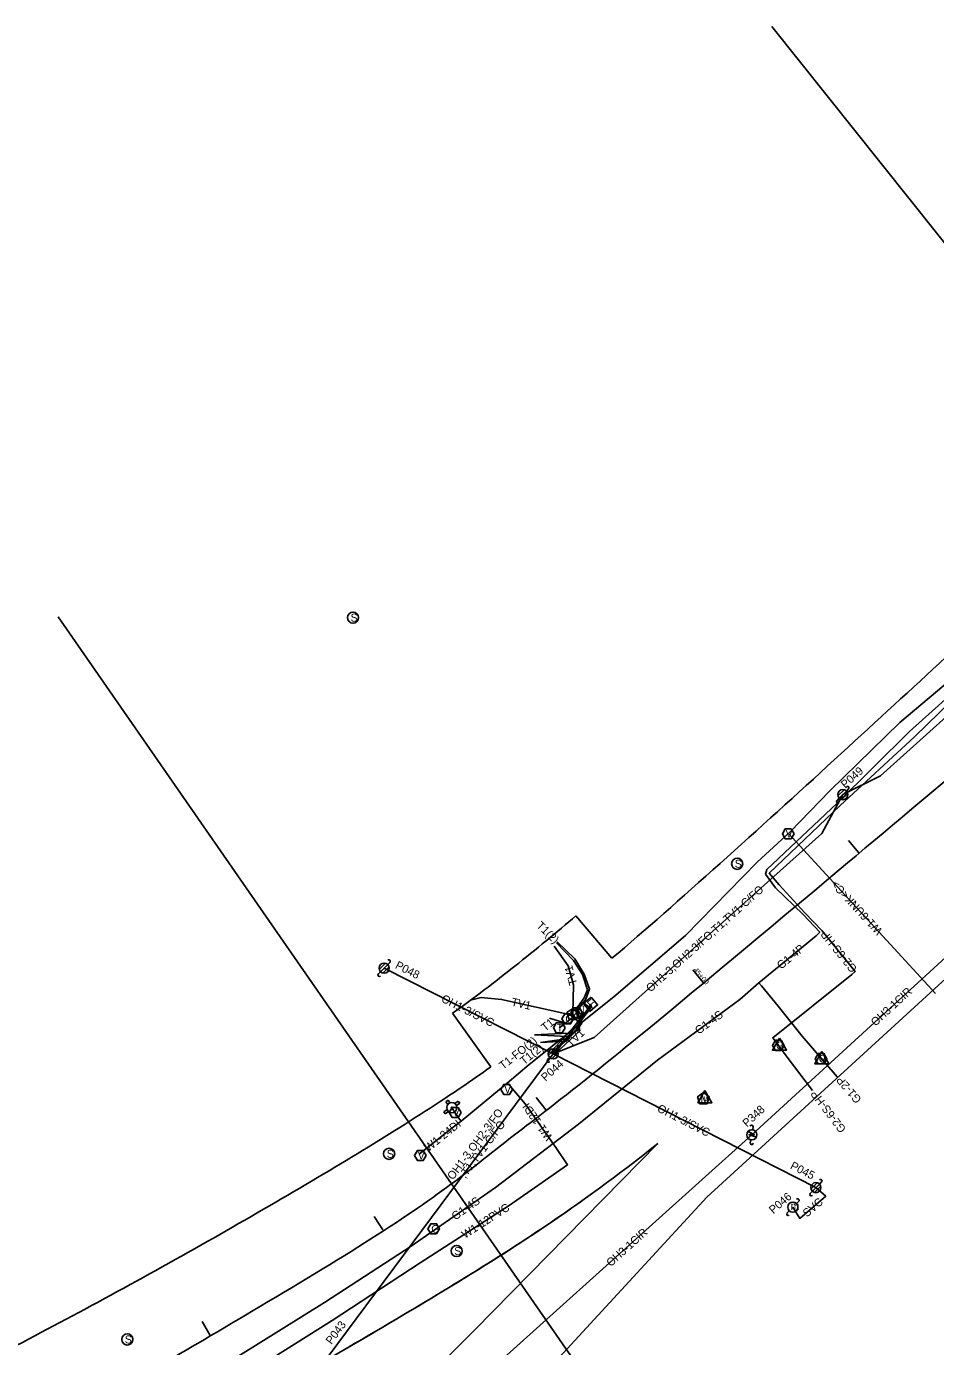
# Model space of a CAD drawing. Extents: x 1991878 to 2008544, y 770238 to 1141211.
# Drawn here: x 2006512 to 2006961, y 1140559 to 1141211 of the extents above; entities that cross this region are included whole.
import ezdxf

# ---------------------------------------------------------------- set-up
doc = ezdxf.new("R2010")
doc.units = 0
for name, color, linetype in [('RD_EX_SU_Gas', 7, 'Continuous'), ('RD_EX_SU_H2O', 7, 'Continuous'), ('RD_EX_SU_Misc', 7, 'Continuous'), ('RD_EX_SU_Ovhd', 7, 'Continuous'), ('RD_EX_SU_Pole', 7, 'Continuous'), ('RD_EX_SU_Sewer', 7, 'Continuous'), ('RD_EX_SU_SwpLmt', 7, 'Continuous'), ('RD_EX_SU_Telecom', 7, 'Continuous'), ('RD_EX_SU_TX_Gas', 7, 'Continuous'), ('RD_EX_SU_TX_H2O', 7, 'Continuous'), ('RD_EX_SU_TX_Ovhd', 7, 'Continuous'), ('RD_EX_SU_TX_Pole', 7, 'Continuous'), ('RD_EX_SU_TX_Telecom', 7, 'Continuous'), ('RD_HC_Cl', 7, 'Continuous')]:
    doc.layers.add(name, color=color, linetype=linetype)

msp = doc.modelspace()

# ---------------------------------------------------------------- linework, layer by layer
at = {"layer": 'RD_EX_SU_Gas'}
for points in [[(2006873.5, 1140738.51), (2006901.73, 1140761.75), (2006903.56, 1140763.42), (2006895.31, 1140772.28), (2006881.72, 1140785.43), (2006876.81, 1140792.08), (2006877.46, 1140794.49), (2006912.15, 1140827.15), (2006947.89, 1140862.5), (2006979.76, 1140891.26), (2006994.33, 1140904.09), (2007020.55, 1140929.45), (2007033.7, 1140941.3), (2007049.4, 1140950.39), (2007052.71, 1140953.47), (2007059.51, 1140959.79), (2007065.74, 1140966.97), (2007091.55, 1141000.3), (2007120.95, 1141038.48), (2007133.17, 1141051.57), (2007138.1, 1141057.67), (2007139.29, 1141058.85)], [(2006899.93, 1140685.24), (2006887.92, 1140701.03), (2006882.38, 1140708.6), (2006880.33, 1140711.39), (2006919.49, 1140742.59), (2006920.99, 1140744.01), (2006904.73, 1140764.19), (2006896.21, 1140773.09), (2006883.59, 1140786.79), (2006878.67, 1140792.56), (2006913.63, 1140826.04), (2006950.43, 1140859.88), (2006981.33, 1140890.04)], [(2006873.5, 1140738.51), (2006864.14, 1140730.25), (2006823.41, 1140700.36), (2006784.38, 1140668.66), (2006743.46, 1140637.37), (2006701.74, 1140608.41), (2006659, 1140580.57), (2006616.24, 1140554.03)], [(2006873.5, 1140738.51), (2006874.73, 1140736.92), (2006883.01, 1140727.02), (2006894.97, 1140712.14), (2006912.21, 1140692)]]:
    msp.add_lwpolyline(points, dxfattribs=at)
for points in [[(2006884.59, 1140705.08), (2006886.03, 1140707.58), (2006884.59, 1140710.08), (2006881.7, 1140710.08), (2006880.26, 1140707.58), (2006881.7, 1140705.08)], [(2006905.67, 1140698.51), (2006907.12, 1140701.01), (2006905.67, 1140703.51), (2006902.79, 1140703.51), (2006901.34, 1140701.01), (2006902.79, 1140698.51)], [(2006714.33, 1140614.5), (2006715.78, 1140617), (2006714.33, 1140619.5), (2006711.45, 1140619.5), (2006710, 1140617), (2006711.45, 1140614.5)]]:
    msp.add_lwpolyline(points, close=True, dxfattribs=at)
at = {"layer": 'RD_EX_SU_H2O'}
for p, q in [((2006960.71, 1140733.22), (2006888.13, 1140812.24)), ((2006720, 1140680.51), (2006718.99, 1140679.76)), ((2006718.99, 1140679.76), (2006719.94, 1140678.47)), ((2006720.97, 1140679.19), (2006720, 1140680.51)), ((2006725.01, 1140680.06), (2006723.38, 1140678.86)), ((2006724.16, 1140677.87), (2006725.76, 1140679.05)), ((2006725.76, 1140679.05), (2006725.01, 1140680.06)), ((2006719.5, 1140675.98), (2006717.92, 1140674.81)), ((2006717.92, 1140674.81), (2006718.67, 1140673.8)), ((2006718.67, 1140673.8), (2006720.21, 1140674.94))]:
    msp.add_line(p, q, dxfattribs=at)
for points in [[(2006705.8, 1140653.82), (2006721.81, 1140666.7), (2006726.48, 1140670.22), (2006749.2, 1140688.87), (2006760.06, 1140698.18), (2006801.94, 1140731.48), (2006837.34, 1140761.88), (2006872.75, 1140798.11), (2006888.92, 1140812.96), (2006908.58, 1140833.31), (2006943.2, 1140866.93), (2006990.62, 1140906.95), (2007018.28, 1140931.47), (2007022.75, 1140936), (2007039, 1140940.71), (2007059.99, 1140944.12), (2007094.46, 1140950.28), (2007154.59, 1140961.32), (2007180.73, 1140965.17), (2007208.8, 1140965.18), (2007231.59, 1140963.11), (2007245.06, 1140960.58), (2007248.47, 1140957.93), (2007283.51, 1140922.44)], [(2006749.33, 1140688.98), (2006750.78, 1140687.21), (2006758.08, 1140678.71), (2006773.28, 1140657.14), (2006779.04, 1140648.68), (2006750.2, 1140628.51), (2006706.32, 1140600.17), (2006662.73, 1140571.78), (2006621.15, 1140545.52)], [(2006726.46, 1140670.2), (2006725.68, 1140671.16), (2006722.55, 1140675.72), (2006721.87, 1140676.84)]]:
    msp.add_lwpolyline(points, dxfattribs=at)
for points in [[(2006890.87, 1140812.01), (2006889.43, 1140814.51), (2006886.54, 1140814.51), (2006885.1, 1140812.01), (2006886.54, 1140809.51), (2006889.43, 1140809.51)], [(2006751.87, 1140685.85), (2006750.43, 1140688.35), (2006747.54, 1140688.35), (2006746.1, 1140685.85), (2006747.54, 1140683.35), (2006750.43, 1140683.35)], [(2006846.11, 1140684.32), (2006843.21, 1140682.21), (2006844.32, 1140678.8), (2006847.9, 1140678.8), (2006849.01, 1140682.21)], [(2006726.42, 1140674.41), (2006724.97, 1140676.9), (2006722.09, 1140676.9), (2006720.64, 1140674.41), (2006722.09, 1140671.91), (2006724.97, 1140671.91)], [(2006709.21, 1140653.18), (2006707.76, 1140655.68), (2006704.88, 1140655.68), (2006703.43, 1140653.18), (2006704.88, 1140650.68), (2006707.76, 1140650.68)]]:
    msp.add_lwpolyline(points, close=True, dxfattribs=at)
for radius in [2.52, 0.315]:
    msp.add_circle((2006721.87, 1140676.84), radius, dxfattribs=at)
for start, end in [(110.76407, 139.73131), (24.20353, 53.17985), (199.85724, 228.83356)]:
    msp.add_arc((2006721.87, 1140676.84), 2.52, start, end, dxfattribs=at)
at = {"layer": 'RD_EX_SU_Misc'}
for points in [[(2006883.65, 1140711.2), (2006880.18, 1140705.2), (2006887.11, 1140705.2)], [(2006904.57, 1140704.52), (2006901.1, 1140698.52), (2006908.03, 1140698.52)], [(2006846.88, 1140685.3), (2006843.41, 1140679.3), (2006850.34, 1140679.3)]]:
    msp.add_lwpolyline(points, close=True, dxfattribs=at)
at = {"layer": 'RD_EX_SU_Ovhd'}
for p, q in [((2007017.86, 1140798.94), (2006870.01, 1140663.43)), ((2006688.44, 1140745.71), (2006771.97, 1140703.38)), ((2006660.79, 1140553.98), (2006771.97, 1140703.38)), ((2006901.69, 1140637.35), (2006771.97, 1140703.38)), ((2006870.01, 1140663.43), (2006747.45, 1140553.1))]:
    msp.add_line(p, q, dxfattribs=at)
for points in [[(2006914.95, 1140831.38), (2006933.52, 1140840.64), (2007047.11, 1140942.67), (2007058.3, 1140960.14)], [(2006771.97, 1140703.38), (2006792.13, 1140711.48), (2006904.68, 1140812.23), (2006914.95, 1140831.38)], [(2006890.31, 1140627.69), (2006893.68, 1140622.18), (2006906.58, 1140633.13), (2006901.69, 1140637.35)]]:
    msp.add_lwpolyline(points, dxfattribs=at)
at = {"layer": 'RD_EX_SU_Pole'}
for p, q in [((2006912.13, 1140828.55), (2006913.19, 1140829.61)), ((2006912.54, 1140830.73), (2006915.6, 1140833.79)), ((2006913.19, 1140829.61), (2006916.72, 1140833.15)), ((2006914.31, 1140828.97), (2006917.37, 1140832.03)), ((2006916.72, 1140833.15), (2006917.78, 1140834.21)), ((2006685.62, 1140742.88), (2006686.68, 1140743.94)), ((2006686.03, 1140745.06), (2006689.09, 1140748.13)), ((2006686.68, 1140743.94), (2006690.21, 1140747.48)), ((2006687.8, 1140743.3), (2006690.86, 1140746.36)), ((2006690.21, 1140747.48), (2006691.27, 1140748.54)), ((2006769.55, 1140702.74), (2006772.61, 1140705.8)), ((2006770.2, 1140701.61), (2006773.74, 1140705.15)), ((2006773.74, 1140705.15), (2006774.8, 1140706.21)), ((2006769.14, 1140700.55), (2006770.2, 1140701.61)), ((2006771.32, 1140700.97), (2006774.38, 1140704.03)), ((2006870.45, 1140665.89), (2006870.72, 1140667.36)), ((2006869.29, 1140659.49), (2006869.56, 1140660.97)), ((2006899.27, 1140636.7), (2006902.33, 1140639.76)), ((2006903.45, 1140639.12), (2006904.51, 1140640.18)), ((2006898.86, 1140634.52), (2006899.92, 1140635.58)), ((2006899.92, 1140635.58), (2006903.45, 1140639.12)), ((2006901.04, 1140634.93), (2006904.1, 1140638)), ((2006892.08, 1140629.46), (2006893.14, 1140630.52)), ((2006887.48, 1140624.87), (2006888.54, 1140625.93))]:
    msp.add_line(p, q, dxfattribs=at)
msp.add_lwpolyline([(2006868.53, 1140664.85), (2006870.36, 1140663.67), (2006868.71, 1140663.5), (2006871.78, 1140662.36), (2006871.78, 1140662.36), (2006869.59, 1140663.4), (2006871.19, 1140663.53)], close=True, dxfattribs=at)
for centre in [(2006914.95, 1140831.38), (2006688.44, 1140745.71), (2006771.97, 1140703.38), (2006870, 1140663.43), (2006901.69, 1140637.35), (2006890.31, 1140627.69)]:
    msp.add_circle(centre, 2.5, dxfattribs=at)
for centre, start, end in [((2006917.25, 1140834.74), 315.01158, 135.01158), ((2006912.66, 1140828.02), 135.01158, 315.01158), ((2006690.74, 1140749.07), 315.01158, 135.01158), ((2006686.15, 1140742.35), 135.01158, 315.01158), ((2006774.27, 1140706.74), 315.01158, 135.01158), ((2006769.67, 1140700.02), 135.01158, 315.01158), ((2006869.98, 1140667.5), 349.68899, 169.68899), ((2006870.02, 1140659.36), 169.68899, 349.68899), ((2006903.98, 1140640.71), 315.01158, 135.01158), ((2006899.39, 1140633.99), 135.01158, 315.01158), ((2006892.61, 1140631.05), 315.01158, 135.01158), ((2006888.01, 1140624.33), 135.01158, 315.01158)]:
    msp.add_arc(centre, 0.75, start, end, dxfattribs=at)
at = {"layer": 'RD_EX_SU_Sewer'}
for centre in [(2006673.1, 1140918.77), (2006862.8, 1140797.25), (2006690.9, 1140654.04), (2006724.29, 1140606.03), (2006561.6, 1140562.39)]:
    msp.add_circle(centre, 2.75, dxfattribs=at)
at = {"layer": 'RD_EX_SU_SwpLmt'}
for p, q in [((2006847.85, 1140632.58), (2007050.24, 1140818.09)), ((2006800.95, 1140750.58), (2006783.18, 1140771.52)), ((2006741.2, 1140697.07), (2006722.26, 1140723.44))]:
    msp.add_line(p, q, dxfattribs=at)
for points in [[(2005780.53, 1139609.9), (2006733.27, 1140567.21), (2006823.57, 1140659.06)], [(2005832.44, 1139605.35), (2006761.62, 1140538.99), (2006847.85, 1140632.58)]]:
    msp.add_lwpolyline(points, dxfattribs=at)
for points in [[(2006800.95, 1140750.58), (2006833.15, 1140777.89), (2006915.9, 1140852.93), (2007008.95, 1140939.06), (2007100.54, 1141022.84), (2007116.49, 1141037.4)], [(2006722.26, 1140723.44), (2006733.19, 1140731.3), (2006752.36, 1140745.81), (2006774.04, 1140763.77), (2006783.18, 1140771.52)], [(2006306.82, 1140473.81), (2006314.46, 1140476.64), (2006388.82, 1140504.33), (2006461.56, 1140535.38), (2006562.87, 1140588.57), (2006665.02, 1140647.19), (2006717.93, 1140680.37), (2006741.2, 1140697.07)], [(2005347.6, 1139821.95), (2005413.49, 1139866.73), (2005588.16, 1139984.08), (2005817.83, 1140151.69), (2006031.43, 1140278.81), (2006110.28, 1140318.03), (2006387.29, 1140416.7), (2006495.91, 1140463.06), (2006601.39, 1140518.44), (2006718.46, 1140585.62), (2006783.57, 1140627.26), (2006823.57, 1140659.06)], [(2005347.6, 1139821.95), (2005413.49, 1139866.73), (2005588.16, 1139984.08), (2005817.83, 1140151.69), (2006031.43, 1140278.81), (2006110.28, 1140318.03), (2006387.29, 1140416.7), (2006495.91, 1140463.06), (2006601.39, 1140518.44), (2006706.19, 1140578.58), (2006762.55, 1140613.92), (2006787.85, 1140632.08)]]:
    msp.add_open_spline(points, degree=3, dxfattribs=at)
at = {"layer": 'RD_EX_SU_Telecom'}
for points in [[(2006781.61, 1140722.84), (2006781.58, 1140723.57), (2006781.89, 1140737.53), (2006779.28, 1140746.93), (2006772.47, 1140756.65)], [(2006783.49, 1140723.61), (2006783.03, 1140724.96), (2006787.29, 1140731.07), (2006788.95, 1140734.99), (2006786.4, 1140742.55), (2006782.01, 1140749.56), (2006773.49, 1140758.14)], [(2006783.49, 1140723.61), (2006783.9, 1140724.94), (2006788.05, 1140730.48), (2006789.85, 1140735.29), (2006787.17, 1140742.69), (2006782.63, 1140750.24), (2006773.9, 1140758.7)], [(2006781.61, 1140722.84), (2006780.6, 1140722.71), (2006746.43, 1140730.32), (2006736.44, 1140731.16), (2006731.12, 1140729.9)], [(2006771.97, 1140703.38), (2006771.55, 1140705.19), (2006782.18, 1140716.73), (2006789.94, 1140726.38), (2006790.36, 1140727.87)], [(2006771.97, 1140703.38), (2006772.24, 1140704.78), (2006782.93, 1140716.25), (2006790.81, 1140726.69), (2006790.36, 1140727.87)], [(2006771.97, 1140703.38), (2006772.96, 1140704.38), (2006774.87, 1140707.47), (2006783.48, 1140715.67), (2006785.61, 1140718.77), (2006783.78, 1140722.61), (2006783.49, 1140723.61)], [(2006771.97, 1140703.38), (2006773.23, 1140703.97), (2006775.45, 1140707.25), (2006783.91, 1140715.33), (2006786.11, 1140718.78), (2006784.28, 1140723.05), (2006783.49, 1140723.61)], [(2006771.97, 1140703.38), (2006773.3, 1140703.7), (2006785.05, 1140714.81), (2006784.3, 1140719.08), (2006782.35, 1140722.03), (2006781.61, 1140722.84)], [(2006774.9, 1140716.28), (2006776.96, 1140717.68), (2006780.89, 1140720.87), (2006783.49, 1140723.61)]]:
    msp.add_lwpolyline(points, dxfattribs=at)
for points in [[(2006790.68, 1140731.39), (2006786.84, 1140728.19), (2006790.04, 1140724.35), (2006793.88, 1140727.55)], [(2006781.61, 1140725.84), (2006778.75, 1140723.77), (2006779.84, 1140720.41), (2006783.37, 1140720.41), (2006784.46, 1140723.77)], [(2006786.38, 1140723.61), (2006784.94, 1140726.11), (2006782.05, 1140726.11), (2006780.61, 1140723.61), (2006782.05, 1140721.11), (2006784.94, 1140721.11)], [(2006786.68, 1140728.68), (2006783.83, 1140726.61), (2006784.92, 1140723.25), (2006788.45, 1140723.25), (2006789.54, 1140726.61)], [(2006777.78, 1140716.28), (2006776.34, 1140718.78), (2006773.45, 1140718.78), (2006772.01, 1140716.28), (2006773.45, 1140713.78), (2006776.34, 1140713.78)], [(2006781.98, 1140720.66), (2006780.54, 1140723.16), (2006777.65, 1140723.16), (2006776.21, 1140720.66), (2006777.65, 1140718.16), (2006780.54, 1140718.16)]]:
    msp.add_lwpolyline(points, close=True, dxfattribs=at)
at = {"layer": 'RD_EX_SU_TX_Telecom'}
for p, q in [((2006770.09, 1140721.1), (2006778.02, 1140718.54)), ((2006762.7, 1140712.74), (2006779.31, 1140713.62)), ((2006762.7, 1140712.74), (2006778.92, 1140711.94)), ((2006765.66, 1140709.03), (2006778.34, 1140710.77)), ((2006765.66, 1140709.03), (2006777.9, 1140709.59))]:
    msp.add_line(p, q, dxfattribs=at)
at = {"layer": 'RD_HC_Cl'}
for p, q in [((2006879.86, 1141210.69), (2007334.1, 1140641.09)), ((2006527.45, 1140919.17), (2006942.87, 1140320.65)), ((2006917.77, 1140808.8), (2006922.9, 1140802.66)), ((2006840.97, 1140744.81), (2006846.08, 1140738.65)), ((2006763.59, 1140681.85), (2006768.51, 1140675.54)), ((2006683.51, 1140623.15), (2006687.88, 1140616.45)), ((2006598.53, 1140571.18), (2006602.58, 1140564.28))]:
    msp.add_line(p, q, dxfattribs=at)
msp.add_open_spline([(2005275.25, 1139802.58), (2005417.33, 1139911.24), (2005548.93, 1140008.55), (2005664.1, 1140090.03), (2005747, 1140153.49), (2005819.82, 1140205.85), (2005880.88, 1140246.35), (2005986.62, 1140308.11), (2006024.68, 1140326.82), (2006100.51, 1140359.48), (2006273.91, 1140424.96), (2006364.15, 1140455.15), (2006461.52, 1140489.97), (2006524.81, 1140519.99), (2006584.45, 1140553.16), (2006699.96, 1140622.09), (2006754.11, 1140664.4), (2006830.67, 1140723.8), (2007317.85, 1141134.95)], degree=2, dxfattribs=at)

# ---------------------------------------------------------------- texts
at = {"layer": 'RD_EX_SU_Gas'}
for p in [(2006881.99, 1140705.7), (2006903.08, 1140699.13), (2006711.74, 1140615.12)]:
    msp.add_text('G', height=3.75, dxfattribs=at).set_placement(p)
at = {"layer": 'RD_EX_SU_H2O'}
for s, p in [('V', (2006886.77, 1140810.13)), ('V', (2006747.77, 1140683.98)), ('M', (2006844.74, 1140679.27)), ('V', (2006722.32, 1140672.53)), ('V', (2006705.11, 1140651.31))]:
    msp.add_text(s, height=3.75, dxfattribs=at).set_placement(p)
at = {"layer": 'RD_EX_SU_Misc'}
for p in [(2006882.89, 1140706), (2006903.81, 1140699.32), (2006846.12, 1140680.1)]:
    msp.add_text('U', height=2.4, dxfattribs=at).set_placement(p)
at = {"layer": 'RD_EX_SU_Pole'}
msp.add_text('m', height=4, rotation=0.01158, dxfattribs=at).set_placement((2006889.12, 1140626.37))
at = {"layer": 'RD_EX_SU_Sewer'}
for p in [(2006671.89, 1140916.81), (2006861.6, 1140795.29), (2006689.7, 1140652.07), (2006723.08, 1140604.07), (2006560.39, 1140560.42)]:
    msp.add_text('S', height=3.93, dxfattribs=at).set_placement(p)
at = {"layer": 'RD_EX_SU_Telecom'}
msp.add_text('F', height=4, rotation=39.79914, dxfattribs=at).set_placement((2006790.77, 1140725.61))
for s, height, p in [('C', 4, (2006780.38, 1140720.84)), ('T', 3.75, (2006782.28, 1140721.73)), ('T', 3.75, (2006785.46, 1140723.45)), ('T', 3.75, (2006773.69, 1140714.4)), ('C', 3.75, (2006777.95, 1140718.79))]:
    msp.add_text(s, height=height, dxfattribs=at).set_placement(p)
at = {"layer": 'RD_EX_SU_TX_Gas'}
for s, rotation, p in [('G2-6S-HP', 128.85332, (2006922.27, 1140745.56)), ('G1-4P', 39.45334, (2006884.45, 1140744.9)), ('G1-4S', 36.27237, (2006843.77, 1140712.79)), ('G1-2P', 130.57229, (2006924.47, 1140681.07)), ('G2-6S-HP', 127.25659, (2006916.81, 1140666.33)), ('G1-4S', 34.76766, (2006723.51, 1140621.06))]:
    msp.add_text(s, height=4, rotation=rotation, dxfattribs=at).set_placement(p)
at = {"layer": 'RD_EX_SU_TX_H2O'}
for s, rotation, p in [('W1-6UNK<C>', 132.56749, (2006934.82, 1140764.35)), ('W1-12DI', 125.17286, (2006771.85, 1140662.32)), ('W1-24DI', 38.83264, (2006710.32, 1140654.86)), ('W1-12PVC', 32.85777, (2006728.39, 1140612.02))]:
    msp.add_text(s, height=4, rotation=rotation, dxfattribs=at).set_placement(p)
at = {"layer": 'RD_EX_SU_TX_Ovhd'}
for s, rotation, p in [('OH1-3,OH2-3/FO,T1,TV1-C/FO', 41.834, (2006820, 1140733.64)), ('OH1-3/SVC', 333.12463, (2006716.29, 1140729.36)), ('OH3-1CIR', 42.50913, (2006931.05, 1140716.82)), ('OH1-3,OH2-3/FO', 53.34448, (2006722.45, 1140640.86)), ('OH1-3/SVC', 333.02126, (2006822.92, 1140675.2)), (',T1,TV1-C/FO', 53.34448, (2006728.54, 1140641.67)), ('SVC', 40.51837, (2006897.25, 1140622.56)), ('OH3-1CIR', 41.99204, (2006800.38, 1140598.06))]:
    msp.add_text(s, height=4, rotation=rotation, dxfattribs=at).set_placement(p)
at = {"layer": 'RD_EX_SU_TX_Pole'}
for s, rotation, p in [('P049', 41.93162, (2006916.19, 1140834.2)), ('P048', 333.12463, (2006693.57, 1140745.86)), ('P044', 41.834, (2006768.15, 1140689.61)), ('P348', 42.50913, (2006867.63, 1140667.02)), ('P045', 333.02126, (2006888.66, 1140646.88)), ('P046', 40.51837, (2006880.6, 1140624.18)), ('P043', 53.34448, (2006662.44, 1140559.63))]:
    msp.add_text(s, height=4, rotation=rotation, dxfattribs=at).set_placement(p)
at = {"layer": 'RD_EX_SU_TX_Telecom'}
for s, rotation, p in [('T1(2)', 315.88263, (2006763.33, 1140766.34)), ('TV1', 105.49226, (2006783.87, 1140737.91)), ('TV1', 347.44452, (2006750.96, 1140727.25)), ('T1', 38.57195, (2006767.98, 1140714.26)), ('T1-FO(2)', 38.57195, (2006747.22, 1140695.42)), ('TV1', 43.3871, (2006780.69, 1140706.49)), ('T1(2)', 38.57195, (2006757.54, 1140697.73))]:
    msp.add_text(s, height=4, rotation=rotation, dxfattribs=at).set_placement(p)
at = {"layer": 'RD_HC_Cl'}
msp.add_text('45+00', height=2.5, rotation=309.63109, dxfattribs=at).set_placement((2006841.02, 1140744.76))

doc.saveas('drawing.dxf')
